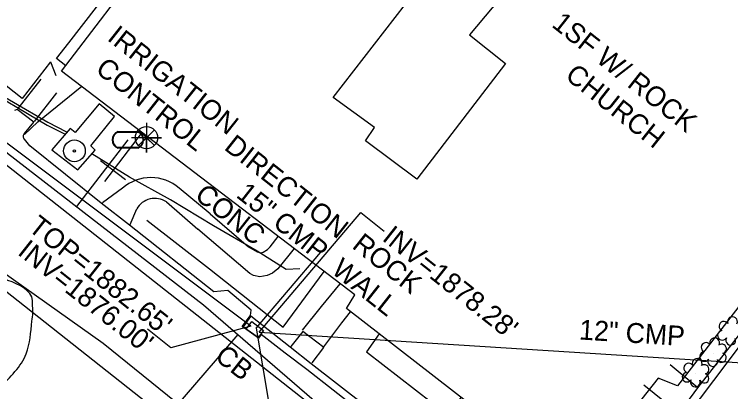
# Model space of a CAD drawing. Extents: x 553786 to 558838, y 502329 to 507342.
# Drawn here: x 557986.9 to 558130.7, y 506577 to 506652.7 of the extents above; entities that cross this region are included whole.
import ezdxf

# ---------------------------------------------------------------- set-up
doc = ezdxf.new("R2010")
doc.units = 0
for name, color, linetype in [('Exist Building Text', 7, 'Continuous'), ('Exist Hydrographic Top of Bank', 7, 'Continuous'), ('Exist Other Culture Church or Cemetery CELL', 7, 'Continuous'), ('Exist Other Culture Gate', 7, 'Continuous'), ('Exist Roads EOP Other Text', 7, 'Continuous'), ('Exist Structure Minor Catch Basin', 7, 'Continuous'), ('Exist Structure Minor Catch Basin Text', 7, 'Continuous'), ('Exist Structure Minor Catch Basin Top Elevation', 7, 'Continuous'), ('Exist Structure Minor Pipes CMP 12 Inch', 7, 'Continuous'), ('Exist Structure Minor Pipes CMP 12 Inch Invert', 7, 'Continuous'), ('Exist Structure Minor Pipes CMP 12 Inch Leader', 7, 'Continuous'), ('Exist Structure Minor Pipes CMP 12 Inch Text', 7, 'Continuous'), ('Exist Structure Minor Pipes CMP 15 Inch', 7, 'Continuous'), ('Exist Structure Minor Pipes CMP 15 Inch Invert', 7, 'Continuous'), ('Exist Structure Minor Pipes CMP 15 Inch Leader', 7, 'Continuous'), ('Exist Structure Minor Pipes CMP 15 Inch Text', 7, 'Continuous'), ('Exist Utilities Other Located Object CELL', 7, 'Continuous'), ('Exist Utilities Water Valve Text', 7, 'Continuous'), ('Exist Vegetation Shrub CELL', 7, 'Continuous'), ('Exist Vertical Profile Ground Line', 7, 'Continuous'), ('Prop CMT Slope Grass', 7, 'Continuous'), ('Prop Drainage Structure Drop Inlet Grate 2 Wide Slots and Sag Grates 840 22 CELL', 7, 'Continuous'), ('Prop Drainage Structure Drop Inlet Grate 840 16 Label', 7, 'Continuous'), ('Prop Drainage Structure Pipe Alternate 24in', 7, 'Continuous'), ('Prop Drainage Structure Pipe Alternate 36in', 7, 'Continuous'), ('Prop Drainage Structure Pipe RCP 15in Class III Label', 7, 'Continuous'), ('Prop Drainage Structure Pipe RCP 15in Class V', 7, 'Continuous'), ('Prop Drainage Structure Plot Symbol 50 Scale', 7, 'Continuous'), ('Prop Drainage Structure Tops and Inverts LABEL', 7, 'Continuous'), ('Prop Earthen Structure Tail Ditch Label', 7, 'Continuous'), ('Prop Erosion Rip Rap Pad Outlet for Jurisdictional Stream CELL', 7, 'Continuous')]:
    doc.layers.add(name, color=color, linetype=linetype)

# ---------------------------------------------------------------- blocks, each defined once
blk = doc.blocks.new('EXIST UTILITIES WATER METER')
at = {"layer": 'Prop Drainage Structure Drop Inlet Grate 840 16 Label'}
blk.add_line((0, 0), (0, 0), dxfattribs=at)
for points in [[(-0.0408, 0.034), (0.0408, 0.034)], [(-0.0408, 0.0312), (0.0408, 0.0312)], [(0.0408, -0.0312), (-0.0413, -0.0312)], [(0.0408, -0.034), (-0.0413, -0.034)]]:
    blk.add_lwpolyline(points, dxfattribs=at)
for centre, radius, start, end in [((-0.0261, -0.0001), 0.0371, 113.178, 245.9794), ((-0.0259, -0.0001), 0.0347, 115.3009, 243.7824), ((0.0259, 0), 0.0371, 293.6483, 66.3084), ((0.0261, 0), 0.0345, 295.1272, 64.8728)]:
    blk.add_arc(centre, radius, start, end, dxfattribs=at)
blk = doc.blocks.new('EXIST DTM SPOT ELEVATION')
at = {"layer": 'Prop Drainage Structure Pipe RCP 15in Class V'}
blk.add_lwpolyline([(0, 0.06), (0, -0.06), (0, 0), (0.06, 0), (-0.06, 0)], dxfattribs=at)

msp = doc.modelspace()

# ---------------------------------------------------------------- linework, layer by layer
at = {"layer": 'Exist Hydrographic Top of Bank'}
msp.add_lwpolyline([(557909.94, 506652.47), (557928.59, 506638.96), (557968.67, 506612.22), (558004.69, 506586.7), (558028.82, 506567.27), (558064.95, 506539.38), (558090.15, 506521.48), (558129.49, 506492.79), (558158.11, 506470.17), (558184.37, 506448.45), (558219.38, 506421.65), (558231.51, 506411.31), (558244.36, 506401.59), (558255.04, 506392.87), (558256.82, 506385.42)], dxfattribs=at)
at = {"layer": 'Exist Other Culture Church or Cemetery CELL'}
for p, q in [((558012.57, 506629.03), (558004.98, 506619.14)), ((558008.77, 506624.07), (558008.77, 506624.07)), ((558009.18, 506619.45), (558004.2, 506623.27))]:
    msp.add_line(p, q, dxfattribs=at)
at = {"layer": 'Exist Other Culture Gate'}
msp.add_line((557994.11, 506643.12), (557995.24, 506640.42), dxfattribs=at)
at = {"layer": 'Exist Structure Minor Catch Basin'}
msp.add_lwpolyline([(558036.88, 506589.28), (558035.82, 506587.84), (558033.39, 506589.52), (558034.57, 506591.08), (558036.88, 506589.28)], dxfattribs=at)
at = {"layer": 'Exist Structure Minor Pipes CMP 12 Inch'}
msp.add_line((558036.01, 506588.91), (558159.83, 506581.09), dxfattribs=at)
at = {"layer": 'Exist Structure Minor Pipes CMP 12 Inch Leader'}
msp.add_lwpolyline([(558036.01, 506588.91), (558056.42, 506612.91), (558061.13, 506609.19)], dxfattribs=at)
at = {"layer": 'Exist Structure Minor Pipes CMP 15 Inch'}
for p, q in [((558034.33, 506590.11), (557893.66, 506695.49)), ((558035.44, 506589.71), (558048.37, 506604.93))]:
    msp.add_line(p, q, dxfattribs=at)
at = {"layer": 'Exist Structure Minor Pipes CMP 15 Inch Leader'}
for points in [[(558034.33, 506590.11), (558018.32, 506585.77), (558013.61, 506589.49)], [(558035.44, 506589.71), (558038.29, 506572.63), (558042.99, 506568.91)]]:
    msp.add_lwpolyline(points, dxfattribs=at)
at = {"layer": 'Exist Utilities Other Located Object CELL'}
for radius in [2.18, 0.24]:
    msp.add_circle((557998.94, 506625.28), radius, dxfattribs=at)
at = {"layer": 'Exist Vegetation Shrub CELL'}
for p, q in [((558127.22, 506584.72), (558127.22, 506584.72)), ((558123.71, 506580.58), (558123.71, 506580.58))]:
    msp.add_line(p, q, dxfattribs=at)
for centre, radius, start, end in [((558131.03, 506591.02), 0.99, 334.8391, 200.4717), ((558129.32, 506590.1), 0.968, 35.8908, 245.4216), ((558129, 506588.27), 0.955, 95.1099, 327.9534), ((558127.45, 506586.76), 0.99, 334.8391, 200.4717), ((558130.68, 506587.29), 0.984, 151.2797, 21.387), ((558125.73, 506585.85), 0.968, 35.8908, 245.4216), ((558128.89, 506585.59), 0.929, 284.4567, 126.0861), ((558125.42, 506584.02), 0.955, 95.1099, 327.9534), ((558128.85, 506583.79), 0.937, 204.9913, 73.4601), ((558123.94, 506582.62), 0.99, 334.8391, 200.4717), ((558127.09, 506583.04), 0.984, 151.2797, 21.387), ((558122.23, 506581.71), 0.968, 35.8908, 245.4216), ((558125.38, 506581.45), 0.929, 284.4567, 126.0861), ((558121.91, 506579.88), 0.955, 95.1099, 327.9534), ((558125.35, 506579.65), 0.937, 204.9913, 73.4601), ((558123.58, 506578.9), 0.984, 151.2797, 21.387)]:
    msp.add_arc(centre, radius, start, end, dxfattribs=at)
at = {"layer": 'Exist Vertical Profile Ground Line'}
for points in [[(557913.08, 506813.34), (557906.87, 506807.42), (557903.76, 506805.42), (557899.23, 506803.08), (557894.14, 506802.12), (557888.57, 506799.22), (557879.13, 506789.51), (557871.12, 506778.79), (557854.78, 506758.76), (557850.03, 506750.87), (557849.87, 506748.38), (557850.85, 506745.69), (557856.3, 506740.46), (557866.07, 506732.89), (557880.79, 506720.64), (557892.02, 506710.14), (557903.01, 506700.73), (557917.46, 506689.55), (557930.53, 506678.94), (557935.08, 506674.75), (557956.23, 506656.91), (557979.42, 506638.7), (557993.48, 506630.45), (557997.11, 506628.63)], [(557949.48, 506708.09), (557943.42, 506699.86), (557933.04, 506685.33), (557930.83, 506681.39), (557931.29, 506679.54), (557935.51, 506675.2), (557956.76, 506657.47), (557979.74, 506639.04), (557993.63, 506631.03), (557997.36, 506629.13)], [(558044.21, 506601.61), (558041.44, 506601.46), (558035.64, 506605.17), (558026.83, 506610.25), (558018.2, 506615.44), (558010, 506619.98), (558002.42, 506624.68)]]:
    msp.add_lwpolyline(points, dxfattribs=at)
at = {"layer": 'Prop CMT Slope Grass'}
msp.add_lwpolyline([(557994.11, 506643.12), (557988.44, 506635.81), (557966.81, 506652.84), (557979.31, 506669.69), (557982.01, 506673.36)], dxfattribs=at)
at = {"layer": 'Prop Drainage Structure Drop Inlet Grate 2 Wide Slots and Sag Grates 840 22 CELL'}
msp.add_lwpolyline([(558014.98, 506629.5), (558011.83, 506626.35), (558013.4, 506627.92), (558014.98, 506626.35), (558011.83, 506629.5)], dxfattribs=at)
msp.add_circle((558013.4, 506627.92), 2.23, dxfattribs=at)
at = {"layer": 'Prop Drainage Structure Pipe Alternate 24in'}
for p, q in [((558009.68, 506627.49), (557999.34, 506614.11)), ((558031.76, 506588.43), (558003.51, 506555.75))]:
    msp.add_line(p, q, dxfattribs=at)
msp.add_lwpolyline([(557781.49, 506782.05), (557812.49, 506757.29), (557852.11, 506727.61), (557885.85, 506702.11), (557901.78, 506690.44), (557913.36, 506682.35), (557957.7, 506647.24), (557985.5, 506624.8), (558024.87, 506594.38), (558058.46, 506565.35), (558080.44, 506547.16), (558106.81, 506525.6), (558129.02, 506509.22), (558127.19, 506506.92), (558119.5, 506495.81), (558106.12, 506476.09), (558102.44, 506470.5), (558089.84, 506453.11)], dxfattribs=at)
at = {"layer": 'Prop Drainage Structure Pipe Alternate 36in'}
for points in [[(557988.92, 506628.75), (557990.8, 506631.06), (557987.43, 506633.55), (557986.88, 506633.39)], [(558138.57, 506507.73), (558130.7, 506513.87), (558118.06, 506524.02), (558105.52, 506533.94), (558080.48, 506553.87), (558056.19, 506573.16), (558045.6, 506581.4), (558041.25, 506584.67), (558036.42, 506588.47), (558035.91, 506587.71), (558032.62, 506590.05), (558034.28, 506592.29), (558034.43, 506593.33), (558029.75, 506597.27), (558026.91, 506596.98), (558010.02, 506610.4), (558004.32, 506614.8), (557989.98, 506626.29), (557988.93, 506627.61)]]:
    msp.add_lwpolyline(points, dxfattribs=at)
msp.add_ellipse((557989.38, 506628.18), major_axis=(0.742, -0.11), ratio=0.961066, start_param=2.387999, end_param=4.204285, dxfattribs=at)
msp.add_spline([(557983.87, 506577.81), (557989.27, 506584.59), (557990.42, 506591.12), (557990.58, 506592.81), (557990.54, 506594.67), (557990.53, 506595.26), (557985.6, 506599.31), (557981.78, 506600.18), (557977.9, 506599.29), (557973.34, 506596.62), (557970.76, 506593.89), (557968.26, 506590.39)], degree=3, dxfattribs=at)
at = {"layer": 'Prop Drainage Structure Pipe RCP 15in Class III Label'}
for p, q in [((557937.38, 506634.72), (558124.11, 506487.8)), ((557972.77, 506632.32), (558065.12, 506559.67))]:
    msp.add_line(p, q, dxfattribs=at)
at = {"layer": 'Prop Drainage Structure Plot Symbol 50 Scale'}
for p, q in [((557992.19, 506639.63), (557987.57, 506633.77)), ((557990.9, 506631.17), (557995.39, 506636.94)), ((558008.58, 506617.77), (558004.55, 506614.88)), ((558026.18, 506612.62), (558019.98, 506617.79)), ((558017.4, 506615.03), (558023.72, 506609.55)), ((558010.11, 506610.5), (558011.44, 506613.64))]:
    msp.add_line(p, q, dxfattribs=at)
for points in [[(558026.18, 506612.62), (558033.85, 506606.04), (558035.61, 506605.06), (558036.45, 506604.83), (558036.86, 506604.97), (558037.72, 506605.52), (558038.23, 506606.01), (558039.87, 506608.08)], [(558043.02, 506605.68), (558039.75, 506601.61), (558038.69, 506600.76), (558037.62, 506600.28), (558036.16, 506600), (558034.87, 506600.27), (558034.18, 506600.7), (558023.72, 506609.55)], [(558116.57, 506565.29), (558124.6, 506575.66), (558135.54, 506590.13), (558144.45, 506601.59), (558156.44, 506603.95), (558156, 506605.23), (558162.9, 506606.13)], [(558046.67, 506582.73), (558048.98, 506585.84), (558044.81, 506589.08), (558042.36, 506586.01)]]:
    msp.add_lwpolyline(points, dxfattribs=at)
for centre, major_axis, ratio, start_param, end_param in [((558014.28, 506611.28), (4.91, 7.13), 0.997891, 6.166312, 7.606717), ((558015.06, 506611.6), (-3.98, -1.21), 0.995725, 3.820051, 5.473756)]:
    msp.add_ellipse(centre, major_axis=major_axis, ratio=ratio, start_param=start_param, end_param=end_param, dxfattribs=at)
at = {"layer": 'Prop Drainage Structure Tops and Inverts LABEL'}
for points in [[(558115.55, 506566.5), (558120.26, 506572.69), (558121.02, 506573.62), (558123.36, 506576.75), (558124.06, 506577.73), (558130.82, 506586.4), (558143.79, 506603.04), (558156, 506605.23)], [(558081.41, 506554.99), (558057.24, 506574.22), (558046.49, 506582.58), (558042.26, 506585.91), (558034.33, 506592.14), (558034.09, 506591.8), (558032.85, 506590.05)]]:
    msp.add_lwpolyline(points, dxfattribs=at)
at = {"layer": 'Prop Earthen Structure Tail Ditch Label'}
for p, q in [((558124.06, 506577.73), (558118.55, 506582.36)), ((558120.26, 506572.69), (558113.26, 506578.25))]:
    msp.add_line(p, q, dxfattribs=at)
for points in [[(557997.21, 506642.36), (557995.35, 506643.82), (557997.8, 506646.93), (558011.48, 506664.6), (558026.62, 506684.22)], [(557994.41, 506625.51), (557999.64, 506621.46), (558003.09, 506625.45), (558002.22, 506626.27), (558007, 506632.18), (558003.92, 506634.73), (557999.06, 506628.96), (557998.09, 506629.75), (557994.41, 506625.51)], [(558044.75, 506589.33), (558048.57, 506594.03), (558052.29, 506598.61)], [(558049.01, 506585.95), (558052.63, 506590.76), (558054.39, 506592.99)], [(558060.14, 506588.55), (558057.56, 506584.96), (558073.98, 506572.25), (558076.59, 506575.81)]]:
    msp.add_lwpolyline(points, dxfattribs=at)
at = {"layer": 'Prop Erosion Rip Rap Pad Outlet for Jurisdictional Stream CELL'}
for points in [[(558106.6, 506680.21), (558179.53, 506624.52), (558164.41, 506605), (558149.47, 506616.17), (558119.97, 506578.13), (558116.13, 506579.67), (558099.22, 506558.28), (558053.56, 506593.64), (558055.21, 506596.38), (557996.37, 506641.26), (558013.95, 506664.31)], [(557988.94, 506628.58), (557991.58, 506631.09), (558000.41, 506638.24)], [(558013.46, 506611.37), (558026.07, 506601.65), (558040.84, 506589.95), (558049.07, 506601.07)]]:
    msp.add_lwpolyline(points, dxfattribs=at)
msp.add_lwpolyline([(558050.87, 506635.97), (558075.76, 506668.17), (558087.36, 506659.48), (558078.27, 506648.57), (558085.46, 506642.78), (558067.69, 506619.59), (558057.4, 506627.26), (558059.16, 506629.99)], close=True, dxfattribs=at)

# ---------------------------------------------------------------- block references
at = {"layer": 'Prop Drainage Structure Drop Inlet Grate 840 16 Label', "xscale": 50, "yscale": 50}
msp.add_blockref('EXIST UTILITIES WATER METER', (558009.68, 506627.49), dxfattribs=at)
at = {"layer": 'Prop Drainage Structure Pipe RCP 15in Class V', "xscale": 50, "yscale": 50}
msp.add_blockref('EXIST DTM SPOT ELEVATION', (558013.4, 506627.92), dxfattribs=at)

# ---------------------------------------------------------------- texts
at = {"layer": 'Exist Building Text'}
for s, p in [('1SF W/ ROCK', (558094.55, 506650.32)), ('CHURCH', (558097.22, 506639.93)), ('ROCK', (558054.46, 506605.92)), ('WALL', (558050.3, 506600.92))]:
    msp.add_text(s, height=4, rotation=321.6667, dxfattribs=at).set_placement(p)
at = {"layer": 'Exist Roads EOP Other Text'}
msp.add_text('CONC', height=4, rotation=321.6667, dxfattribs=at).set_placement((558022.85, 506615.88))
at = {"layer": 'Exist Structure Minor Catch Basin Text'}
msp.add_text('CB', height=4, rotation=321.6667, dxfattribs=at).set_placement((558026.89, 506583.58))
at = {"layer": 'Exist Structure Minor Catch Basin Top Elevation'}
msp.add_text("TOP=1882.65'", height=4, rotation=321.6667, dxfattribs=at).set_placement((557989.44, 506609.49))
at = {"layer": 'Exist Structure Minor Pipes CMP 12 Inch Invert'}
msp.add_text("INV=1878.28'", height=4, rotation=321.6667, dxfattribs=at).set_placement((558060.52, 506607.46))
at = {"layer": 'Exist Structure Minor Pipes CMP 12 Inch Text'}
msp.add_text('12" CMP', height=4, rotation=356.3853, dxfattribs=at).set_placement((558100.17, 506587.46))
at = {"layer": 'Exist Structure Minor Pipes CMP 15 Inch Invert'}
for s, p in [('DIRECTION', (558028.79, 506625.69)), ("INV=1876.00'", (557987.33, 506604.63))]:
    msp.add_text(s, height=4, rotation=321.6667, dxfattribs=at).set_placement(p)
at = {"layer": 'Exist Structure Minor Pipes CMP 15 Inch Text'}
msp.add_text('15" CMP', height=4, rotation=321.6667, dxfattribs=at).set_placement((558031.2, 506616.15))
at = {"layer": 'Exist Utilities Water Valve Text'}
for s, p in [('IRRIGATION', (558005.33, 506647.61)), ('CONTROL', (558002.93, 506641.22))]:
    msp.add_text(s, height=4, rotation=321.6667, dxfattribs=at).set_placement(p)

doc.saveas('drawing.dxf')
